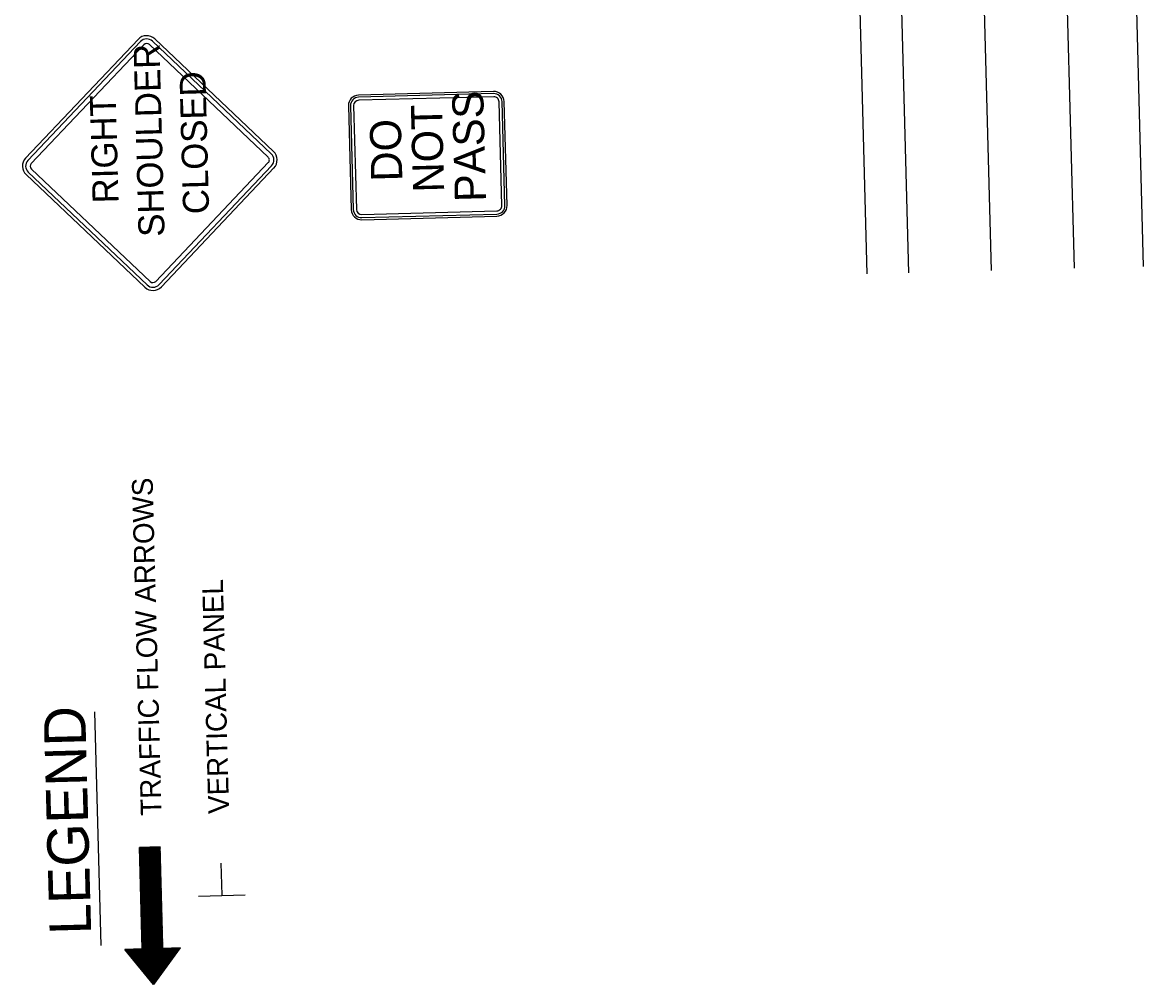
# Model space of a CAD drawing. Extents: x 1930579 to 1931593, y 596452 to 598537.
# Drawn here: x 1930645.6 to 1930969.4, y 597040.5 to 597318.3 of the extents above; entities that cross this region are included whole.
import ezdxf

# ---------------------------------------------------------------- set-up
doc = ezdxf.new("R2010")
doc.units = 0
for name, color, linetype in [('P_TC_Signs_Permanent', 7, 'Continuous'), ('P_TC_Signs_Temporary', 7, 'Continuous'), ('R_Annotation', 7, 'Continuous'), ('R_Draft', 7, 'Continuous'), ('R_Legend_MOT', 7, 'Continuous')]:
    doc.layers.add(name, color=color, linetype=linetype)

msp = doc.modelspace()

# ---------------------------------------------------------------- linework, layer by layer
at = {"layer": 'P_TC_Signs_Permanent'}
for p, q in [((1930781.67, 597298.38), (1930742.69, 597297.34)), ((1930781.69, 597297.78), (1930742.7, 597296.74)), ((1930781.71, 597296.88), (1930742.73, 597295.84)), ((1930784.06, 597265.44), (1930783.25, 597295.43)), ((1930784.96, 597265.46), (1930784.15, 597295.45)), ((1930785.56, 597265.48), (1930784.75, 597295.47)), ((1930739.77, 597294.26), (1930740.57, 597264.27)), ((1930740.37, 597294.27), (1930741.17, 597264.28)), ((1930741.27, 597294.3), (1930742.07, 597264.31)), ((1930743.61, 597262.85), (1930782.6, 597263.9)), ((1930743.64, 597261.95), (1930782.62, 597263)), ((1930743.65, 597261.35), (1930782.64, 597262.4))]:
    msp.add_line(p, q, dxfattribs=at)
for centre, radius, start, end in [((1930742.77, 597294.34), 3, 91.5377, 181.5377), ((1930742.77, 597294.34), 2.4, 91.5377, 181.5377), ((1930742.77, 597294.34), 1.5, 91.5377, 181.5377), ((1930781.75, 597295.38), 3, 1.5377, 91.5377), ((1930781.75, 597295.38), 2.4, 1.5377, 91.5377), ((1930781.75, 597295.38), 1.5, 1.5377, 91.5377), ((1930743.57, 597264.35), 3, 181.5377, 271.5377), ((1930743.57, 597264.35), 2.4, 181.5377, 271.5377), ((1930743.57, 597264.35), 1.5, 181.5377, 271.5377), ((1930782.56, 597265.4), 1.5, 271.5377, 1.5377), ((1930782.56, 597265.4), 2.4, 271.5377, 1.5377), ((1930782.56, 597265.4), 3, 271.5377, 1.5377)]:
    msp.add_arc(centre, radius, start, end, dxfattribs=at)
at = {"layer": 'P_TC_Signs_Temporary'}
for p, q in [((1930646.56, 597279.14), (1930679.07, 597313.43)), ((1930647.24, 597278.49), (1930679.75, 597312.79)), ((1930648.2, 597277.59), (1930680.7, 597311.89)), ((1930682.29, 597311.93), (1930716.59, 597279.43)), ((1930683.19, 597312.88), (1930717.49, 597280.38)), ((1930683.84, 597313.56), (1930718.13, 597281.06)), ((1930682.54, 597243.5), (1930648.24, 597276)), ((1930716.63, 597277.84), (1930684.13, 597243.54)), ((1930717.58, 597276.93), (1930685.08, 597242.64)), ((1930718.26, 597276.29), (1930685.76, 597241.99)), ((1930680.99, 597241.86), (1930646.69, 597274.37)), ((1930681.63, 597242.54), (1930647.34, 597275.05))]:
    msp.add_line(p, q, dxfattribs=at)
for centre, radius, start, end in [((1930681.52, 597311.11), 3.38, 46.5377, 136.5377), ((1930681.52, 597311.11), 2.44, 46.5377, 136.5377), ((1930681.52, 597311.11), 1.12, 46.5377, 136.5377), ((1930649.01, 597276.82), 3.38, 136.5377, 226.5377), ((1930715.81, 597278.61), 1.13, 316.5377, 46.5377), ((1930715.81, 597278.61), 2.44, 316.5377, 46.5377), ((1930715.81, 597278.61), 3.38, 316.5377, 46.5377), ((1930649.01, 597276.82), 2.44, 136.5377, 226.5377), ((1930649.01, 597276.82), 1.13, 136.5377, 226.5377), ((1930683.31, 597244.31), 1.12, 226.5377, 316.5377), ((1930683.31, 597244.31), 3.38, 226.5377, 316.5377), ((1930683.31, 597244.31), 2.44, 226.5377, 316.5377)]:
    msp.add_arc(centre, radius, start, end, dxfattribs=at)
at = {"layer": 'R_Annotation'}
for p, q in [((1930679.44, 597080.13), (1930685.58, 597074.31)), ((1930679.44, 597079.99), (1930685.59, 597074.17)), ((1930679.45, 597079.85), (1930685.59, 597074.03)), ((1930679.45, 597079.71), (1930685.59, 597073.88)), ((1930679.46, 597079.56), (1930685.6, 597073.74)), ((1930679.46, 597079.42), (1930685.6, 597073.6)), ((1930679.46, 597079.28), (1930685.61, 597073.46)), ((1930679.47, 597079.14), (1930685.61, 597073.32)), ((1930679.47, 597079), (1930685.61, 597073.18)), ((1930679.47, 597078.86), (1930685.62, 597073.04)), ((1930679.48, 597078.72), (1930685.62, 597072.89)), ((1930679.48, 597078.58), (1930685.63, 597072.75)), ((1930679.49, 597078.43), (1930685.63, 597072.61)), ((1930679.49, 597078.29), (1930685.63, 597072.47)), ((1930679.56, 597080.15), (1930685.58, 597074.45)), ((1930679.71, 597080.15), (1930685.58, 597074.59)), ((1930679.85, 597080.16), (1930685.57, 597074.73)), ((1930679.99, 597080.16), (1930685.57, 597074.87)), ((1930680.13, 597080.17), (1930685.56, 597075.02)), ((1930680.27, 597080.17), (1930685.56, 597075.16)), ((1930680.41, 597080.17), (1930685.56, 597075.3)), ((1930680.55, 597080.18), (1930685.55, 597075.44)), ((1930680.7, 597080.18), (1930685.55, 597075.58)), ((1930680.84, 597080.18), (1930685.55, 597075.72)), ((1930680.98, 597080.19), (1930685.54, 597075.86)), ((1930681.12, 597080.19), (1930685.54, 597076)), ((1930681.26, 597080.2), (1930685.53, 597076.15)), ((1930681.4, 597080.2), (1930685.53, 597076.29)), ((1930681.54, 597080.2), (1930685.53, 597076.43)), ((1930681.69, 597080.21), (1930685.52, 597076.57)), ((1930681.83, 597080.21), (1930685.52, 597076.71)), ((1930681.97, 597080.21), (1930685.52, 597076.85)), ((1930682.11, 597080.22), (1930685.51, 597076.99)), ((1930682.25, 597080.22), (1930685.51, 597077.14)), ((1930682.39, 597080.23), (1930685.5, 597077.28)), ((1930682.53, 597080.23), (1930685.5, 597077.42)), ((1930682.67, 597080.23), (1930685.5, 597077.56)), ((1930682.82, 597080.24), (1930685.49, 597077.7)), ((1930682.96, 597080.24), (1930685.49, 597077.84)), ((1930683.1, 597080.25), (1930685.48, 597077.98)), ((1930683.24, 597080.25), (1930685.48, 597078.13)), ((1930683.38, 597080.25), (1930685.48, 597078.27)), ((1930683.52, 597080.26), (1930685.47, 597078.41)), ((1930683.66, 597080.26), (1930685.47, 597078.55)), ((1930683.81, 597080.26), (1930685.47, 597078.69)), ((1930683.95, 597080.27), (1930685.46, 597078.83)), ((1930684.09, 597080.27), (1930685.46, 597078.97)), ((1930684.23, 597080.28), (1930685.45, 597079.12)), ((1930684.37, 597080.28), (1930685.45, 597079.26)), ((1930684.51, 597080.28), (1930685.45, 597079.4)), ((1930684.65, 597080.29), (1930685.44, 597079.54)), ((1930684.8, 597080.29), (1930685.44, 597079.68)), ((1930684.94, 597080.29), (1930685.44, 597079.82)), ((1930685.08, 597080.3), (1930685.43, 597079.96)), ((1930685.22, 597080.3), (1930685.43, 597080.1)), ((1930685.36, 597080.31), (1930685.42, 597080.25)), ((1930679.49, 597078.15), (1930685.64, 597072.33)), ((1930679.5, 597078.01), (1930685.64, 597072.19)), ((1930679.5, 597077.87), (1930685.64, 597072.05)), ((1930679.5, 597077.73), (1930685.65, 597071.91)), ((1930679.51, 597077.59), (1930685.65, 597071.76)), ((1930679.51, 597077.44), (1930685.66, 597071.62)), ((1930679.52, 597077.3), (1930685.66, 597071.48)), ((1930679.52, 597077.16), (1930685.66, 597071.34)), ((1930679.52, 597077.02), (1930685.67, 597071.2)), ((1930679.53, 597076.88), (1930685.67, 597071.06)), ((1930679.53, 597076.74), (1930685.67, 597070.92)), ((1930679.54, 597076.6), (1930685.68, 597070.77)), ((1930679.54, 597076.45), (1930685.68, 597070.63)), ((1930679.54, 597076.31), (1930685.69, 597070.49)), ((1930679.55, 597076.17), (1930685.69, 597070.35)), ((1930679.55, 597076.03), (1930685.69, 597070.21)), ((1930679.55, 597075.89), (1930685.7, 597070.07)), ((1930679.56, 597075.75), (1930685.7, 597069.93)), ((1930679.56, 597075.61), (1930685.7, 597069.78)), ((1930679.57, 597075.47), (1930685.71, 597069.64)), ((1930679.57, 597075.32), (1930685.71, 597069.5)), ((1930679.57, 597075.18), (1930685.72, 597069.36)), ((1930679.58, 597075.04), (1930685.72, 597069.22)), ((1930679.58, 597074.9), (1930685.72, 597069.08)), ((1930679.58, 597074.76), (1930685.73, 597068.94)), ((1930679.59, 597074.62), (1930685.73, 597068.8)), ((1930679.59, 597074.48), (1930685.74, 597068.65)), ((1930679.6, 597074.33), (1930685.74, 597068.51)), ((1930679.6, 597074.19), (1930685.74, 597068.37)), ((1930679.6, 597074.05), (1930685.75, 597068.23)), ((1930679.61, 597073.91), (1930685.75, 597068.09)), ((1930679.61, 597073.77), (1930685.75, 597067.95)), ((1930679.61, 597073.63), (1930685.76, 597067.81)), ((1930679.62, 597073.49), (1930685.76, 597067.66)), ((1930679.62, 597073.34), (1930685.77, 597067.52)), ((1930679.63, 597073.2), (1930685.77, 597067.38)), ((1930679.63, 597073.06), (1930685.77, 597067.24)), ((1930679.63, 597072.92), (1930685.78, 597067.1)), ((1930679.64, 597072.78), (1930685.78, 597066.96)), ((1930679.64, 597072.64), (1930685.78, 597066.82)), ((1930679.65, 597072.5), (1930685.79, 597066.67)), ((1930679.65, 597072.36), (1930685.79, 597066.53)), ((1930679.65, 597072.21), (1930685.8, 597066.39)), ((1930679.66, 597072.07), (1930685.8, 597066.25)), ((1930679.66, 597071.93), (1930685.8, 597066.11)), ((1930679.66, 597071.79), (1930685.81, 597065.97)), ((1930679.67, 597071.65), (1930685.81, 597065.83)), ((1930679.67, 597071.51), (1930685.81, 597065.68)), ((1930679.68, 597071.37), (1930685.82, 597065.54)), ((1930679.68, 597071.22), (1930685.82, 597065.4)), ((1930679.68, 597071.08), (1930685.83, 597065.26)), ((1930679.69, 597070.94), (1930685.83, 597065.12)), ((1930679.69, 597070.8), (1930685.83, 597064.98)), ((1930679.69, 597070.66), (1930685.84, 597064.84)), ((1930679.7, 597070.52), (1930685.84, 597064.7)), ((1930679.7, 597070.38), (1930685.85, 597064.55)), ((1930679.71, 597070.23), (1930685.85, 597064.41)), ((1930679.71, 597070.09), (1930685.85, 597064.27)), ((1930679.71, 597069.95), (1930685.86, 597064.13)), ((1930679.72, 597069.81), (1930685.86, 597063.99)), ((1930679.72, 597069.67), (1930685.86, 597063.85)), ((1930679.72, 597069.53), (1930685.87, 597063.71)), ((1930679.73, 597069.39), (1930685.87, 597063.56)), ((1930679.73, 597069.24), (1930685.88, 597063.42)), ((1930679.74, 597069.1), (1930685.88, 597063.28)), ((1930679.74, 597068.96), (1930685.88, 597063.14)), ((1930679.74, 597068.82), (1930685.89, 597063)), ((1930679.75, 597068.68), (1930685.89, 597062.86)), ((1930679.75, 597068.54), (1930685.89, 597062.72)), ((1930679.76, 597068.4), (1930685.9, 597062.57)), ((1930679.76, 597068.26), (1930685.9, 597062.43)), ((1930679.76, 597068.11), (1930685.91, 597062.29)), ((1930679.77, 597067.97), (1930685.91, 597062.15)), ((1930679.77, 597067.83), (1930685.91, 597062.01)), ((1930679.77, 597067.69), (1930685.92, 597061.87)), ((1930679.78, 597067.55), (1930685.92, 597061.73)), ((1930679.78, 597067.41), (1930685.92, 597061.59)), ((1930679.79, 597067.27), (1930685.93, 597061.44)), ((1930679.79, 597067.12), (1930685.93, 597061.3)), ((1930679.79, 597066.98), (1930685.94, 597061.16)), ((1930679.8, 597066.84), (1930685.94, 597061.02)), ((1930679.8, 597066.7), (1930685.94, 597060.88)), ((1930679.8, 597066.56), (1930685.95, 597060.74)), ((1930679.81, 597066.42), (1930685.95, 597060.6)), ((1930679.81, 597066.28), (1930685.96, 597060.45)), ((1930679.82, 597066.13), (1930685.96, 597060.31)), ((1930679.82, 597065.99), (1930685.96, 597060.17)), ((1930679.82, 597065.85), (1930685.97, 597060.03)), ((1930679.83, 597065.71), (1930685.97, 597059.89)), ((1930679.83, 597065.57), (1930685.97, 597059.75)), ((1930679.84, 597065.43), (1930685.98, 597059.61)), ((1930679.84, 597065.29), (1930685.98, 597059.46)), ((1930679.84, 597065.15), (1930685.99, 597059.32)), ((1930679.85, 597065), (1930685.99, 597059.18)), ((1930679.85, 597064.86), (1930685.99, 597059.04)), ((1930679.85, 597064.72), (1930686, 597058.9)), ((1930679.86, 597064.58), (1930686, 597058.76)), ((1930679.86, 597064.44), (1930686, 597058.62)), ((1930679.87, 597064.3), (1930686.01, 597058.48)), ((1930679.87, 597064.16), (1930686.01, 597058.33)), ((1930679.87, 597064.01), (1930686.02, 597058.19)), ((1930679.88, 597063.87), (1930686.02, 597058.05)), ((1930679.88, 597063.73), (1930686.02, 597057.91)), ((1930679.88, 597063.59), (1930686.03, 597057.77)), ((1930679.89, 597063.45), (1930686.03, 597057.63)), ((1930679.89, 597063.31), (1930686.04, 597057.49)), ((1930679.9, 597063.17), (1930686.04, 597057.34)), ((1930679.9, 597063.02), (1930686.04, 597057.2)), ((1930679.9, 597062.88), (1930686.05, 597057.06)), ((1930679.91, 597062.74), (1930686.05, 597056.92)), ((1930679.91, 597062.6), (1930686.05, 597056.78)), ((1930679.91, 597062.46), (1930686.06, 597056.64)), ((1930679.92, 597062.32), (1930686.06, 597056.5)), ((1930679.92, 597062.18), (1930686.07, 597056.35)), ((1930679.93, 597062.03), (1930686.07, 597056.21)), ((1930679.93, 597061.89), (1930686.07, 597056.07)), ((1930679.93, 597061.75), (1930686.08, 597055.93)), ((1930679.94, 597061.61), (1930686.08, 597055.79)), ((1930679.94, 597061.47), (1930686.08, 597055.65)), ((1930679.95, 597061.33), (1930686.09, 597055.51)), ((1930679.95, 597061.19), (1930686.09, 597055.36)), ((1930679.95, 597061.05), (1930686.1, 597055.22)), ((1930679.96, 597060.9), (1930686.1, 597055.08)), ((1930679.96, 597060.76), (1930686.1, 597054.94)), ((1930679.96, 597060.62), (1930686.11, 597054.8)), ((1930679.97, 597060.48), (1930686.11, 597054.66)), ((1930679.97, 597060.34), (1930686.11, 597054.52)), ((1930679.98, 597060.2), (1930686.12, 597054.38)), ((1930679.98, 597060.06), (1930686.12, 597054.23)), ((1930679.98, 597059.91), (1930686.13, 597054.09)), ((1930679.99, 597059.77), (1930686.13, 597053.95)), ((1930679.99, 597059.63), (1930686.13, 597053.81)), ((1930679.99, 597059.49), (1930686.14, 597053.67)), ((1930680, 597059.35), (1930686.14, 597053.53)), ((1930680, 597059.21), (1930686.15, 597053.39)), ((1930680.01, 597059.07), (1930686.15, 597053.24)), ((1930680.01, 597058.92), (1930686.15, 597053.1)), ((1930680.01, 597058.78), (1930686.16, 597052.96)), ((1930680.02, 597058.64), (1930686.16, 597052.82)), ((1930680.02, 597058.5), (1930686.16, 597052.68)), ((1930680.02, 597058.36), (1930686.17, 597052.54)), ((1930680.03, 597058.22), (1930686.17, 597052.4)), ((1930680.03, 597058.08), (1930686.18, 597052.25)), ((1930680.04, 597057.94), (1930686.18, 597052.11)), ((1930680.04, 597057.79), (1930686.18, 597051.97)), ((1930680.04, 597057.65), (1930686.19, 597051.83)), ((1930680.05, 597057.51), (1930686.19, 597051.69)), ((1930680.05, 597057.37), (1930686.19, 597051.55)), ((1930680.06, 597057.23), (1930686.2, 597051.41)), ((1930680.06, 597057.09), (1930686.2, 597051.27)), ((1930680.06, 597056.95), (1930686.21, 597051.12)), ((1930680.07, 597056.8), (1930686.21, 597050.98)), ((1930680.07, 597056.66), (1930689.05, 597048.16)), ((1930680.07, 597056.52), (1930688.99, 597048.07)), ((1930680.08, 597056.38), (1930688.93, 597047.99)), ((1930680.08, 597056.24), (1930688.87, 597047.91)), ((1930680.09, 597056.1), (1930688.81, 597047.83)), ((1930680.09, 597055.96), (1930688.75, 597047.75)), ((1930680.09, 597055.81), (1930688.69, 597047.67)), ((1930680.1, 597055.67), (1930688.63, 597047.59)), ((1930680.1, 597055.53), (1930688.57, 597047.5)), ((1930680.1, 597055.39), (1930688.51, 597047.42)), ((1930680.11, 597055.25), (1930688.45, 597047.34)), ((1930680.11, 597055.11), (1930688.39, 597047.26)), ((1930680.12, 597054.97), (1930688.33, 597047.18)), ((1930680.12, 597054.83), (1930688.27, 597047.1)), ((1930680.12, 597054.68), (1930688.22, 597047.01)), ((1930680.13, 597054.54), (1930688.16, 597046.93)), ((1930680.13, 597054.4), (1930688.1, 597046.85)), ((1930680.13, 597054.26), (1930688.04, 597046.77)), ((1930680.14, 597054.12), (1930687.98, 597046.69)), ((1930680.14, 597053.98), (1930687.92, 597046.61)), ((1930680.15, 597053.84), (1930687.86, 597046.53)), ((1930680.15, 597053.69), (1930687.8, 597046.44)), ((1930680.15, 597053.55), (1930687.74, 597046.36)), ((1930680.16, 597053.41), (1930687.68, 597046.28)), ((1930680.16, 597053.27), (1930687.62, 597046.2)), ((1930680.17, 597053.13), (1930687.56, 597046.12)), ((1930680.17, 597052.99), (1930687.5, 597046.04)), ((1930680.17, 597052.85), (1930687.44, 597045.96)), ((1930680.18, 597052.7), (1930687.38, 597045.87)), ((1930680.18, 597052.56), (1930687.32, 597045.79)), ((1930680.18, 597052.42), (1930687.27, 597045.71)), ((1930675.34, 597050.68), (1930684.53, 597041.96)), ((1930675.41, 597050.47), (1930684.47, 597041.88)), ((1930675.48, 597050.68), (1930684.59, 597042.04)), ((1930675.62, 597050.69), (1930684.65, 597042.13)), ((1930675.76, 597050.69), (1930684.71, 597042.21)), ((1930675.9, 597050.69), (1930684.77, 597042.29)), ((1930675.9, 597049.87), (1930684.41, 597041.8)), ((1930676.04, 597050.7), (1930684.83, 597042.37)), ((1930676.18, 597050.7), (1930684.89, 597042.45)), ((1930676.33, 597050.71), (1930684.95, 597042.53)), ((1930676.39, 597049.27), (1930684.36, 597041.72)), ((1930676.47, 597050.71), (1930685.01, 597042.61)), ((1930676.61, 597050.71), (1930685.07, 597042.7)), ((1930676.75, 597050.72), (1930685.13, 597042.78)), ((1930676.89, 597050.72), (1930685.19, 597042.86)), ((1930677.03, 597050.72), (1930685.25, 597042.94)), ((1930677.17, 597050.73), (1930685.31, 597043.02)), ((1930677.32, 597050.73), (1930685.36, 597043.1)), ((1930677.46, 597050.74), (1930685.42, 597043.18)), ((1930677.6, 597050.74), (1930685.48, 597043.27)), ((1930677.74, 597050.74), (1930685.54, 597043.35)), ((1930677.88, 597050.75), (1930685.6, 597043.43)), ((1930678.02, 597050.75), (1930685.66, 597043.51)), ((1930678.16, 597050.75), (1930685.72, 597043.59)), ((1930678.3, 597050.76), (1930685.78, 597043.67)), ((1930678.45, 597050.76), (1930685.84, 597043.76)), ((1930678.59, 597050.77), (1930685.9, 597043.84)), ((1930678.73, 597050.77), (1930685.96, 597043.92)), ((1930678.87, 597050.77), (1930686.02, 597044)), ((1930679.01, 597050.78), (1930686.08, 597044.08)), ((1930679.15, 597050.78), (1930686.14, 597044.16)), ((1930679.29, 597050.79), (1930686.2, 597044.24)), ((1930679.44, 597050.79), (1930686.26, 597044.33)), ((1930679.58, 597050.79), (1930686.32, 597044.41)), ((1930679.72, 597050.8), (1930686.37, 597044.49)), ((1930679.86, 597050.8), (1930686.43, 597044.57)), ((1930680, 597050.8), (1930686.49, 597044.65)), ((1930680.14, 597050.81), (1930686.55, 597044.73)), ((1930680.19, 597052.28), (1930687.21, 597045.63)), ((1930680.19, 597052.14), (1930687.15, 597045.55)), ((1930680.2, 597052), (1930687.09, 597045.47)), ((1930680.2, 597051.86), (1930687.03, 597045.39)), ((1930680.2, 597051.71), (1930686.97, 597045.3)), ((1930680.21, 597051.57), (1930686.91, 597045.22)), ((1930680.21, 597051.43), (1930686.85, 597045.14)), ((1930680.21, 597051.29), (1930686.79, 597045.06)), ((1930680.22, 597051.15), (1930686.73, 597044.98)), ((1930680.22, 597051.01), (1930686.67, 597044.9)), ((1930680.23, 597050.87), (1930686.61, 597044.81)), ((1930686.22, 597050.97), (1930689.11, 597048.24)), ((1930686.36, 597050.97), (1930689.17, 597048.32)), ((1930686.5, 597050.98), (1930689.22, 597048.4)), ((1930686.65, 597050.98), (1930689.28, 597048.48)), ((1930686.79, 597050.99), (1930689.34, 597048.56)), ((1930686.93, 597050.99), (1930689.4, 597048.64)), ((1930687.07, 597050.99), (1930689.46, 597048.73)), ((1930687.21, 597051), (1930689.52, 597048.81)), ((1930687.35, 597051), (1930689.58, 597048.89)), ((1930687.49, 597051.01), (1930689.64, 597048.97)), ((1930687.64, 597051.01), (1930689.7, 597049.05)), ((1930687.78, 597051.01), (1930689.76, 597049.13)), ((1930687.92, 597051.02), (1930689.82, 597049.22)), ((1930688.06, 597051.02), (1930689.88, 597049.3)), ((1930688.2, 597051.02), (1930689.94, 597049.38)), ((1930688.34, 597051.03), (1930690, 597049.46)), ((1930688.48, 597051.03), (1930690.06, 597049.54)), ((1930688.62, 597051.04), (1930690.12, 597049.62)), ((1930688.77, 597051.04), (1930690.17, 597049.7)), ((1930688.91, 597051.04), (1930690.23, 597049.79)), ((1930689.05, 597051.05), (1930690.29, 597049.87)), ((1930689.19, 597051.05), (1930690.35, 597049.95)), ((1930689.33, 597051.05), (1930690.41, 597050.03)), ((1930689.47, 597051.06), (1930690.47, 597050.11)), ((1930689.61, 597051.06), (1930690.53, 597050.19)), ((1930689.76, 597051.07), (1930690.59, 597050.27)), ((1930689.9, 597051.07), (1930690.65, 597050.36)), ((1930690.04, 597051.07), (1930690.71, 597050.44)), ((1930690.18, 597051.08), (1930690.77, 597050.52)), ((1930690.32, 597051.08), (1930690.83, 597050.6)), ((1930690.46, 597051.09), (1930690.89, 597050.68)), ((1930690.6, 597051.09), (1930690.95, 597050.76)), ((1930690.75, 597051.09), (1930691.01, 597050.85)), ((1930690.89, 597051.1), (1930691.07, 597050.93)), ((1930691.03, 597051.1), (1930691.13, 597051.01)), ((1930691.17, 597051.1), (1930691.18, 597051.09)), ((1930676.88, 597048.66), (1930684.3, 597041.64)), ((1930677.37, 597048.06), (1930684.24, 597041.55)), ((1930677.86, 597047.46), (1930684.18, 597041.47)), ((1930678.36, 597046.85), (1930684.12, 597041.39)), ((1930678.85, 597046.25), (1930684.06, 597041.31)), ((1930679.34, 597045.65), (1930684, 597041.23)), ((1930679.83, 597045.04), (1930683.94, 597041.15)), ((1930680.32, 597044.44), (1930683.88, 597041.07)), ((1930680.81, 597043.84), (1930683.82, 597040.98)), ((1930681.3, 597043.23), (1930683.76, 597040.9)), ((1930681.79, 597042.63), (1930683.7, 597040.82)), ((1930682.29, 597042.03), (1930683.64, 597040.74)), ((1930682.78, 597041.42), (1930683.58, 597040.66)), ((1930683.27, 597040.82), (1930683.52, 597040.58))]:
    msp.add_line(p, q, dxfattribs=at)
at = {"layer": 'R_Draft'}
for p, q in [((1930925.48, 597246.69), (1930913.83, 597680.54)), ((1930949.41, 597247.33), (1930937.76, 597681.18)), ((1930969.35, 597247.87), (1930957.71, 597681.72)), ((1930889.59, 597245.72), (1930877.94, 597679.58)), ((1930901.55, 597246.05), (1930889.9, 597679.9)), ((1930685.42, 597080.31), (1930679.44, 597080.15)), ((1930680.23, 597050.81), (1930679.44, 597080.15)), ((1930686.21, 597050.97), (1930685.42, 597080.31)), ((1930703.27, 597066.36), (1930703.03, 597075.55)), ((1930709.98, 597066.35), (1930696.52, 597065.98)), ((1930680.23, 597050.81), (1930675.24, 597050.68)), ((1930683.5, 597040.54), (1930675.24, 597050.68)), ((1930691.2, 597051.1), (1930683.5, 597040.54)), ((1930691.2, 597051.1), (1930686.21, 597050.97))]:
    msp.add_line(p, q, dxfattribs=at)
at = {"layer": 'R_Legend_MOT'}
msp.add_line((1930668.4, 597051.83), (1930666.59, 597119.32), dxfattribs=at)

# ---------------------------------------------------------------- texts
at = {"layer": 'P_TC_Signs_Permanent'}
for s, rotation, p in [('PASS', 91.5377, (1930779.52, 597266.61)), ('NOT', 91.4973, (1930767.44, 597269.34)), ('DO', 91.5377, (1930755.36, 597272.5))]:
    msp.add_text(s, height=9, rotation=rotation, dxfattribs=at).set_placement(p)
at = {"layer": 'P_TC_Signs_Temporary'}
for s, p in [('SHOULDER', (1930686.7, 597256.53)), ('CLOSED', (1930699.56, 597263.06)), ('RIGHT', (1930673.42, 597266.19))]:
    msp.add_text(s, height=7.5, rotation=91.5377, dxfattribs=at).set_placement(p)
at = {"layer": 'R_Legend_MOT'}
for s, height, p in [('TRAFFIC FLOW ARROWS', 6, (1930685.84, 597089.38)), ('VERTICAL PANEL', 6, (1930705.33, 597089.91)), ('LEGEND', 12, (1930665.51, 597055.11))]:
    msp.add_text(s, height=height, rotation=91.5377, dxfattribs=at).set_placement(p)

doc.saveas('drawing.dxf')
